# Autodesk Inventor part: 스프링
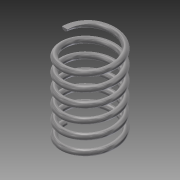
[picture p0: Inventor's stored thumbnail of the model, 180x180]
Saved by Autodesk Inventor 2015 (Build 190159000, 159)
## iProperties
Created: 2015-10
Part Number: 스프링
Material: Steel, Mild
Document SubType Name: Modeling
Designer: youjin06
Mass: 128.854 g
Surface Area: 132.996 cm^2
Volume: 16.4145 cm^3
Density: 7.85 g/cm^3
Appearance: Semi-Polished
Author: youjin06
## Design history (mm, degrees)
sketch "Sketch2"
  geometry: L1 (0, 0)-(22.5, 0); L2 (22.5, 0)-(22.5, 73.25); L3 (22.5, 73.25)-(0, 73.25); L4 (0, 73.25)-(0, 0); C1 r 2.5 at (22.5, 0)
  constraints: 8 end point, 2 parallel, 1 centre point, 1 coincident, 1 horizontal, 1 perpendicular
  dimensions: "d0" = 73.25 distance between parallel lines of L3 L1 (derived); "d1" = 45 diameter of L2 L4; "d2" = 5 diameter of C1
coil "Coil1" sketch "Sketch2" pitch "d3" = 10; turns "d5" = 6; dims "d4" = 73.25 (= d0), "d6" = 0, angle "d7" = 90 deg, angle "d8" = 90 deg, "d9" = 0, "d10" = 0
sketch "Sketch3"
  geometry: L1 (-25, 0)-(-20, 0) reference; 1 further point
  constraints: 1 horizontal alignment
extrude "Extrusion1" cut sketch "Sketch3" distance "d11" = 10; taper "d12" = 0 deg
workplane "Work Plane1"
sketch "Sketch4"
  geometry: L1 (25, 0)-(20, 0) reference; 1 further point
  constraints: 1 horizontal alignment
extrude "Extrusion2" cut sketch "Sketch4" distance "d13" = 10; taper "d14" = 0 deg
body "Solid1"
node "Project Cut Edges1"
node "Project Cut Edges2"
